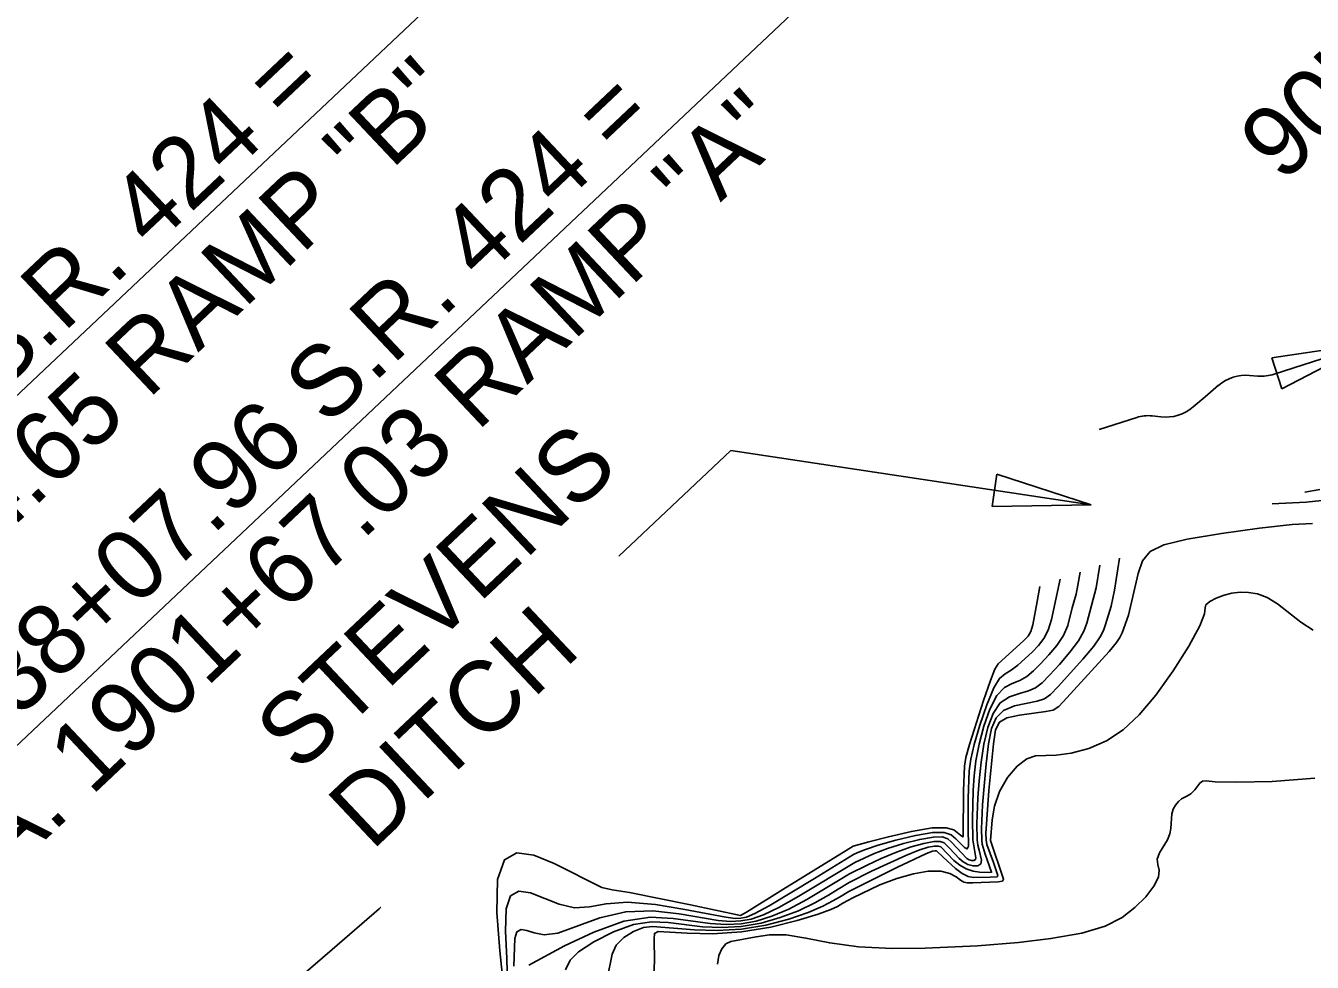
# Model space of a CAD drawing. Extents: x -291892836 to 2945206, y -477993085 to 1832792.
# Drawn here: x 1849500 to 1850179, y 542838 to 543332 of the extents above; entities that cross this region are included whole.
import ezdxf

# ---------------------------------------------------------------- set-up
doc = ezdxf.new("R2010")
doc.units = 0
for name, color, linetype in [('DT_X_Contour_Minor', 7, 'Continuous'), ('Level 31', 7, 'Continuous'), ('Level 40', 7, 'Continuous')]:
    doc.layers.add(name, color=color, linetype=linetype)

msp = doc.modelspace()

# ---------------------------------------------------------------- linework, layer by layer
at = {"layer": 'DT_X_Contour_Minor'}
for points in [[(1850174.9, 543085.88), (1850182.88, 543087.18)], [(1850183.92, 543081.47), (1850175.52, 543080.51), (1850157.66, 543079.74)], [(1850178.99, 543069.27), (1850168.18, 543068.71), (1850150.97, 543066.77), (1850130.88, 543064), (1850112.81, 543060.96), (1850100.52, 543057.97), (1850093.28, 543054.46), (1850089.26, 543049.63), (1850086.82, 543042.99), (1850081.78, 543020.91), (1850078.38, 543011.63), (1850077.3, 543009.13), (1850075.51, 543006.48), (1850071.54, 543001.83), (1850049.31, 542977.25), (1850045.02, 542972.76), (1850042.03, 542970.81), (1850038.09, 542970.02), (1850024.15, 542968.13), (1850017.61, 542966.67), (1850013.61, 542964.53), (1850011.58, 542960.48), (1850010.42, 542953.04), (1850008.13, 542928.4), (1850006.51, 542905.64), (1850006.56, 542902.31), (1850007.07, 542899.89), (1850010.44, 542890.4), (1850012.72, 542883.46), (1850012.37, 542882.89), (1850008.78, 542882.6), (1849999.88, 542882.5), (1849997.06, 542883.08), (1849993.95, 542884.6), (1849990.39, 542887.27), (1849984.01, 542893.21)], [(1850076.96, 543051), (1850074.47, 543034.07), (1850072.66, 543025.64), (1850069.62, 543016.02), (1850068.56, 543012.91), (1850066.9, 543009.5), (1850063.5, 543004.64), (1850057.71, 542997.69), (1850044.73, 542983.29), (1850040.57, 542979.03), (1850037.37, 542976.72), (1850033.51, 542975.47), (1850021.55, 542972.99), (1850015.86, 542970.63), (1850011.94, 542966.82), (1850009.51, 542961.09), (1850007.91, 542952.96), (1850006.6, 542942.39), (1850004.75, 542920.76), (1850004.14, 542908.22), (1850004.27, 542902.31), (1850004.59, 542900.14), (1850006.19, 542894.79), (1850009.52, 542885.2), (1850007.74, 542885.14), (1850003.13, 542885.29), (1849999.7, 542885.78), (1849996.07, 542886.96), (1849992.65, 542889), (1849989.64, 542891.48), (1849982.62, 542898.58), (1849981.37, 542899.02), (1849979.31, 542899.01), (1849976.02, 542898.39), (1849971.11, 542896.86), (1849964.22, 542894.14), (1849946.17, 542885.74), (1849934.31, 542879.78), (1849928.48, 542876.24), (1849923.31, 542873.06), (1849916.15, 542869.06), (1849907.54, 542864.92), (1849897.95, 542861.27), (1849887.75, 542858.42), (1849877.29, 542856.63), (1849866.88, 542856.05), (1849856.82, 542856.44), (1849838.65, 542858.64), (1849829.97, 542859.06), (1849820.49, 542857.67), (1849809.82, 542853.82), (1849799.47, 542848.53), (1849791.41, 542843.23), (1849786.93, 542838.78), (1849784.53, 542833.81)], [(1849982.41, 542901.44), (1849984.47, 542900.72), (1849987.28, 542898.01), (1849992.39, 542892.52), (1849994.56, 542890.73), (1849997.03, 542889.35), (1849999.73, 542888.61), (1850002.17, 542888.67), (1850003.77, 542889.66), (1850004.14, 542891.6), (1850002.89, 542896.89), (1850002.3, 542899.5), (1850001.95, 542902.36), (1850001.76, 542910.79), (1850002.28, 542924.59), (1850002.92, 542933.56), (1850003.92, 542943.26), (1850005.39, 542952.88), (1850007.45, 542961.69), (1850010.28, 542969.1), (1850014.1, 542974.58), (1850018.95, 542977.84), (1850024.17, 542979.63), (1850028.93, 542980.92), (1850032.7, 542982.64), (1850036.13, 542985.3), (1850040.14, 542989.34), (1850045.33, 542994.95), (1850050.84, 543001.33), (1850055.45, 543007.46), (1850058.29, 543012.52), (1850059.83, 543016.7), (1850064.78, 543035.43), (1850066.73, 543047.35)], [(1849753.84, 542825.83), (1849753.53, 542839.69), (1849752.87, 542854.07), (1849753.19, 542865.88), (1849755.56, 542872.79), (1849759.92, 542875.25), (1849765.95, 542874.43), (1849781.24, 542868.36), (1849789.3, 542866.43), (1849797.14, 542866.94), (1849805.96, 542868.58), (1849817.32, 542869.46), (1849831.97, 542868.21), (1849847.5, 542865.63), (1849869.21, 542861.46), (1849874.04, 542860.88), (1849877.04, 542860.96), (1849880.01, 542861.59), (1849884.51, 542863.49), (1849892.08, 542867.59), (1849916.01, 542881.99), (1849936.51, 542894.53), (1849938.84, 542895.63), (1849942.96, 542897.27), (1849949.61, 542899.49), (1849959.02, 542902.17), (1849969.4, 542904.69), (1849978.46, 542906.24), (1849984.49, 542906.27), (1849988.14, 542904.99), (1849990.67, 542902.85), (1849995.17, 542898.29), (1849996.65, 542897.59), (1849997.26, 542898.98), (1849997.07, 542908.32), (1849997.12, 542924.38), (1849997.71, 542938.72), (1849998.57, 542944.99), (1850000.36, 542952.73), (1850003.32, 542962.9), (1850006.96, 542973.67), (1850010.6, 542982.49), (1850013.75, 542987.55), (1850016.67, 542990.03), (1850019.78, 542991.83), (1850023.38, 542994.46), (1850030.98, 543001.42), (1850034.29, 543004.9), (1850037.09, 543008.62), (1850039.36, 543013.09), (1850041.07, 543018.56), (1850045.75, 543039.88)], [(1849757.26, 542835.59), (1849757.69, 542850.28), (1849758.88, 542853.75), (1849761.07, 542854.98), (1849764.1, 542854.57), (1849767.94, 542853.24), (1849773.18, 542852.29), (1849780.55, 542853.14), (1849802.69, 542861.14), (1849816.35, 542864.41), (1849830.7, 542864.83), (1849844.47, 542863.26), (1849865.08, 542859.79), (1849871.66, 542859.27), (1849877.12, 542859.52), (1849882.59, 542860.53), (1849888.99, 542862.75), (1849897.23, 542866.7), (1849907.67, 542872.56), (1849937.24, 542890.37), (1849947.09, 542894.9), (1849954.48, 542897.71), (1849963.05, 542900.4), (1849971.61, 542902.59), (1849978.74, 542903.83), (1849983.45, 542903.85), (1849986.31, 542902.85), (1849988.29, 542901.17), (1849996.37, 542892.47), (1849997.62, 542891.75), (1849998.96, 542891.39), (1850000.17, 542891.42), (1850000.97, 542891.91), (1850001.15, 542892.91), (1849999.63, 542902.42), (1849999.39, 542913.37), (1849999.82, 542928.41), (1850000.32, 542936.14), (1850001.25, 542944.12), (1850002.88, 542952.81), (1850005.38, 542962.3), (1850008.62, 542971.39), (1850012.35, 542978.54), (1850016.35, 542982.7), (1850020.42, 542984.83), (1850024.36, 542986.38), (1850028.04, 542988.55), (1850031.68, 542991.56), (1850035.56, 542995.38), (1850039.81, 542999.93), (1850043.97, 543004.98), (1850047.4, 543010.27), (1850049.68, 543015.54), (1850052.1, 543024.81), (1850054.09, 543032.09), (1850055.1, 543036.8), (1850056.29, 543043.63)], [(1850179.25, 543013.09), (1850172.72, 543017.2), (1850160.55, 543026.99), (1850155.04, 543030.24), (1850149.91, 543032.12), (1850145.14, 543032.97), (1850140.68, 543033.1), (1850136.42, 543032.6), (1850132.23, 543031.53), (1850128.12, 543029.95), (1850124.69, 543028.15), (1850122.64, 543026.43), (1850122.25, 543024.74), (1850121.9, 543021.62), (1850119.51, 543015.27), (1850113.64, 543004.61), (1850105.3, 542991.55), (1850096.14, 542978.75), (1850087.43, 542968.35), (1850078.98, 542960.46), (1850070.2, 542954.67), (1850060.81, 542950.62), (1850051.6, 542948.12), (1850043.61, 542947), (1850032.76, 542946.76), (1850028.15, 542945.19), (1850023.01, 542941.21), (1850017.89, 542935.22), (1850013.7, 542927.94), (1850011.09, 542920.17), (1850009.77, 542912.93), (1850008.92, 542902.02), (1850015.86, 542881.61), (1850015.22, 542880.58), (1850012.9, 542880.26), (1849999.57, 542879.69), (1849996.67, 542879.67), (1849994.78, 542880.02), (1849993.07, 542881.01), (1849990.79, 542882.76), (1849987.45, 542884.64), (1849982.63, 542885.87), (1849976.08, 542885.82), (1849968.18, 542884.48), (1849959.47, 542881.97), (1849950.57, 542878.54), (1849936.29, 542871.82), (1849930.93, 542868.86), (1849928.17, 542867.11), (1849924.64, 542865.56), (1849917.85, 542863.15), (1849906.91, 542859.79), (1849892.94, 542856.3), (1849877.52, 542853.73), (1849862.27, 542852.81), (1849848.82, 542853.06), (1849833.41, 542853.88), (1849831.44, 542852.92), (1849831.28, 542850.05)], [(1849989.61, 542907.58), (1849993.13, 542904.83), (1849994.31, 542903.92), (1849994.45, 542904.42), (1849994.72, 542928.14), (1849995.11, 542941.3), (1849995.9, 542945.86), (1849997.84, 542952.65), (1850005.29, 542975.96), (1850008.84, 542986.45), (1850011.15, 542992.41), (1850012.92, 542995.23), (1850026.39, 543007.46), (1850028.77, 543009.88), (1850030.22, 543012.26), (1850031.31, 543015.9), (1850033.62, 543028.06), (1850035.03, 543036.06)], [(1849864.69, 542836.76), (1849865.47, 542841.23), (1849867.06, 542844.88), (1849869.23, 542847.41), (1849871.82, 542848.72), (1849885.15, 542851.2), (1849892.32, 542852.22), (1849901.05, 542852.18), (1849911.47, 542850.48), (1849924.03, 542847.98), (1849939.24, 542845.87), (1849956.96, 542845.04), (1849974.41, 542845.17), (1850002.12, 542846.34), (1850023.68, 542848.23), (1850040.8, 542850.21), (1850057.12, 542853.05), (1850069.51, 542856.82), (1850078.42, 542861.41), (1850085.2, 542866.66), (1850090.88, 542872.34), (1850095.22, 542877.9), (1850097.65, 542882.71), (1850097.95, 542886.37), (1850097.25, 542889.31), (1850096.99, 542892.17), (1850098.23, 542895.44), (1850102.44, 542902.39), (1850103.65, 542905.51), (1850104.14, 542908.35), (1850104.73, 542916.12), (1850105.43, 542918.49), (1850106.63, 542920.67), (1850108.15, 542922.53), (1850109.77, 542923.95), (1850112.61, 542925.45), (1850114.76, 542926.55), (1850116.76, 542928.78), (1850119.45, 542932.3), (1850120.87, 542933.4), (1850122.73, 542933.48), (1850127.63, 542933.01), (1850138.74, 542932.7), (1850157.69, 542933.19), (1850180.09, 542934.85)], [(1849752.66, 542816.76), (1849749.79, 542843.79), (1849748.28, 542863.98), (1849748.7, 542881.49), (1849752.25, 542891.84), (1849758.78, 542895.52), (1849767.79, 542894.29), (1849778.55, 542889.94), (1849803.75, 542877.24), (1849809.24, 542876.02), (1849818.29, 542874.5), (1849850.52, 542868), (1849876.96, 542862.41), (1849880.03, 542864.23), (1849899.19, 542876.06), (1849932.65, 542896.78), (1849936.4, 542898.93), (1849944.75, 542901.27), (1849954.99, 542903.95), (1849967.2, 542906.79), (1849978.17, 542908.65), (1849985.48, 542908.74), (1849989.61, 542907.58)], [(1849765.12, 542836.22), (1849783.92, 542846.34), (1849799.42, 542853.7), (1849815.37, 542859.37), (1849829.44, 542861.45), (1849841.45, 542860.89), (1849860.95, 542858.11), (1849869.27, 542857.66), (1849877.21, 542858.07), (1849885.17, 542859.48), (1849893.47, 542862.01), (1849902.39, 542865.81), (1849911.91, 542870.81), (1849927.81, 542880.31), (1849934.55, 542884.43), (1849943.73, 542889.04), (1849951.22, 542892.52), (1849959.35, 542895.92), (1849967.08, 542898.63), (1849973.81, 542900.49), (1849979.03, 542901.42), (1849982.41, 542901.44)], [(1849984.01, 542893.21), (1849980.34, 542896.61), (1849979.59, 542896.6), (1849978.22, 542896.29), (1849975.14, 542895.09), (1849959.49, 542887.76), (1849934.08, 542875.13), (1849929.15, 542872.17), (1849925.74, 542870.08), (1849920.4, 542867.31), (1849912.69, 542864.04), (1849902.43, 542860.53), (1849890.34, 542857.36), (1849877.37, 542855.18), (1849864.49, 542854.44), (1849852.69, 542854.76), (1849830.53, 542856.69), (1849825.67, 542856), (1849820.36, 542854.01), (1849815.24, 542850.85), (1849811.31, 542846.77), (1849809.2, 542841.93), (1849806.6, 542829.02)], [(1849686.61, 542866.56), (1849686.83, 542866.65), (1849686.12, 542865.92), (1849661.23, 542844.38), (1849628.28, 542815.98)], [(1849831.28, 542850.05), (1849831.58, 542838.28), (1849831.17, 542831.59)]]:
    msp.add_lwpolyline(points, dxfattribs=at)
at = {"layer": 'Level 31'}
for p, q in [((1850157.4, 543156.8), (1850209.11, 543164.49)), ((1850158.73, 543148.19), (1850209.11, 543164.49)), ((1850209.11, 543164.49), (1850162.68, 543140.46)), ((1850162.68, 543140.46), (1850157.4, 543156.8)), ((1850129.39, 543142.25), (1850122.28, 543136.21)), ((1850150.08, 543147.15), (1850145.66, 543147.51)), ((1850122.28, 543136.21), (1850115.98, 543130.81)), ((1850066.22, 543118.87), (1850086.13, 543125.31)), ((1850098.83, 543125.58), (1850094.22, 543126.11))]:
    msp.add_line(p, q, dxfattribs=at)
for centre, radius, start, end in [((1850143.9, 543125.17), 22.4, 85.52713, 130.37099), ((1850151.84, 543169.49), 22.4, 265.56596, 287.92598), ((1850101.43, 543147.85), 22.4, 263.39329, 310.50176), ((1850092.05, 543107.05), 19.2, 83.44317, 107.92598)]:
    msp.add_arc(centre, radius, start, end, dxfattribs=at)
at = {"layer": 'Level 40'}
for p, q in [((1849233.62, 542890.32), (1849832.52, 543455.57)), ((1849408.75, 542870.96), (1850007.65, 543436.21)), ((1849812.69, 543052.01), (1849871.79, 543107.79)), ((1849871.79, 543107.79), (1850062.07, 543079.17)), ((1850009.79, 543078.36), (1850012.35, 543095.34)), ((1850012.35, 543095.34), (1850062.07, 543079.17)), ((1850062.07, 543079.17), (1850009.79, 543078.36))]:
    msp.add_line(p, q, dxfattribs=at)

# ---------------------------------------------------------------- texts
for s, p in [('90" A', (1850163.04, 543248.5)), ('STA. 37+66.96 S.R. 424 =', (1849230.54, 542897.01)), ('STA. 1870+24.65 RAMP "B"', (1849269.15, 542856.11)), ('STA. 38+07.96 S.R. 424 =', (1849404.27, 542879.92)), ('STA. 1901+67.03 RAMP "A"', (1849442.88, 542839.01)), ('STEVENS', (1849643.57, 542937)), ('DITCH', (1849682.18, 542896.09))]:
    msp.add_text(s, height=37.5, rotation=43.3446, dxfattribs=at).set_placement(p)

doc.saveas('drawing.dxf')
